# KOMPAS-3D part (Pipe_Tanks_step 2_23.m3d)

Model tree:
1. X Axis
2. Y Axis
3. Z Axis  (labels: T-Bend Dn 50; Pipe Dn 50)
     Òîëùèíà ñòåíêè 1 = 1

Referenced files in C:\Documents and Settings\kashirsky\Мои документы\Camtasia Studio\Pipelines3D\Tanks\: Tanks_step 2.a3d
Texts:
  Pipe Dn 50
  Steel ASTM A295
  Three Point Plane
  Plane at Angle
  Line and Point Plane
  Axis through Two Vertices
  Axis of Feature
  Axis of Conical Surface
  Axis through Edge
  Trim by Surface
  Trim by Sketch
  Feature with No History
  Intersection Axis of Two Planes
  Two Line Plane
  Line and Face Plane
  Bend by line
  Hole in sheet body
  Cut in sheet body
  Point in CM
  Linear Dimension from Line to Point
  Surface Finish Symbol
  Geometric Tolerance Symbol
  Leader #1
  Leader #2
  Leader #3
  Shape Deviations and Datum
  Node point number
  Mark of coordination axis
  Node point designation
  Mark/Reference designation with leader
  Mark/reference designation on line
  Mark/Reference designation without leader
  T-Bend Dn 50
  Plane of section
